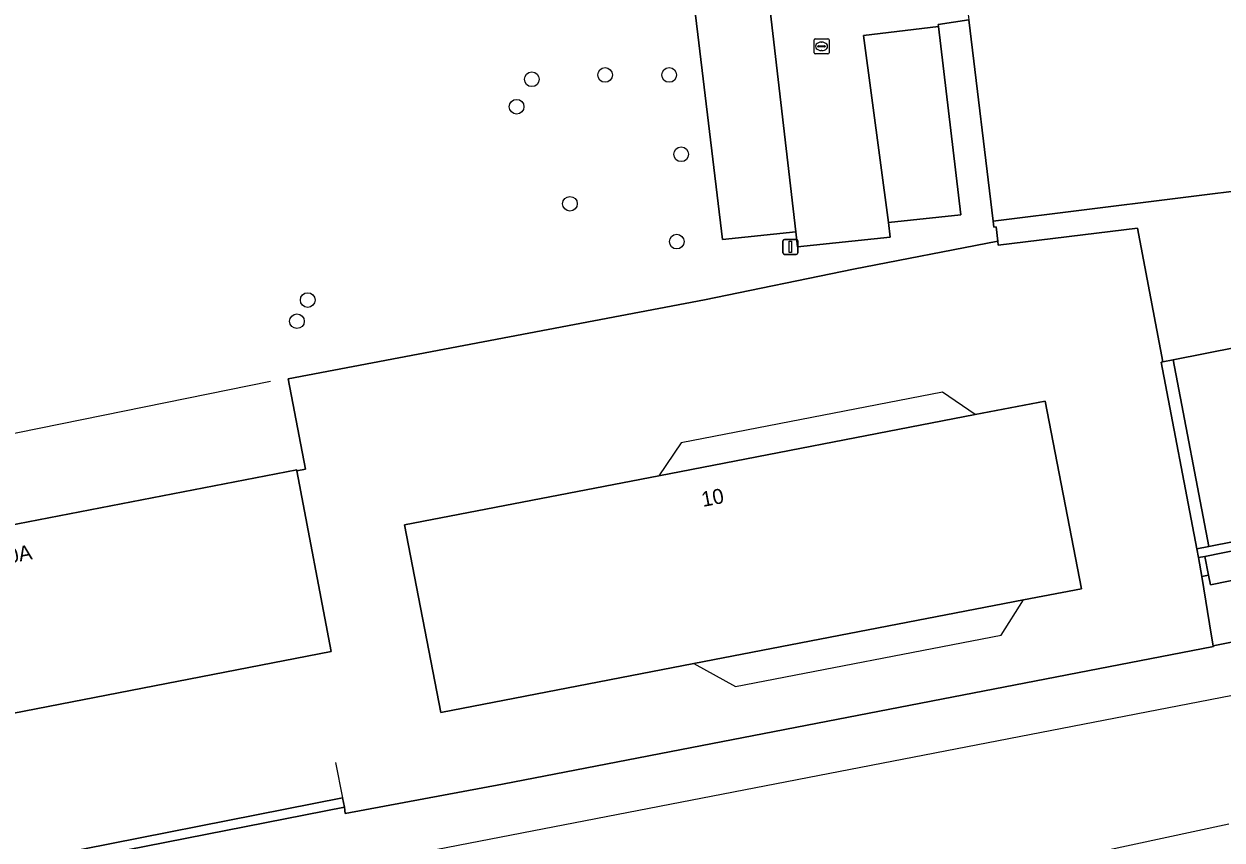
# Model space of a CAD drawing. Extents: x 161477 to 163040, y 383680 to 384871.
# Drawn here: x 161860.2 to 161940, y 383906.2 to 383960.6 of the extents above; entities that cross this region are included whole.
import ezdxf

# ---------------------------------------------------------------- set-up
doc = ezdxf.new("R2010")
doc.units = 0
for name, color, linetype in [('IMGEO_Boom', 7, 'Continuous'), ('IMGEO_Erf', 7, 'Continuous'), ('IMGEO_Groenvoorziening', 7, 'Continuous'), ('IMGEO_Hek', 7, 'Continuous'), ('IMGEO_Kolk', 7, 'Continuous'), ('IMGEO_Lichtmast', 7, 'Continuous'), ('IMGEO_Muur', 7, 'Continuous'), ('IMGEO_Pand', 7, 'Continuous'), ('IMGEO_Pand_nummerreeks', 7, 'Continuous'), ('IMGEO_Pand_overbouw', 7, 'Continuous'), ('IMGEO_Parkeervlak_halfverhard', 7, 'Continuous'), ('IMGEO_Parkeervlak_open', 7, 'Continuous'), ('IMGEO_Rijbaan_lokaal_open', 7, 'Continuous'), ('IMGEO_Spoor', 7, 'Continuous'), ('IMGEO_Spoorbaan_halfverhard', 7, 'Continuous'), ('IMGEO_Terreindeel_onvherhard', 7, 'Continuous'), ('IMGEO_Terreindeel_open', 7, 'Continuous')]:
    doc.layers.add(name, color=color, linetype=linetype)

msp = doc.modelspace()

# ---------------------------------------------------------------- linework, layer by layer
at = {"layer": 'IMGEO_Boom'}
for centre in [(161894.02, 383956.922), (161898.906, 383957.215), (161903.179, 383957.215), (161893.006, 383955.098), (161903.979, 383951.925), (161896.564, 383948.624), (161903.687, 383946.106), (161879.074, 383942.207), (161878.356, 383940.799)]:
    msp.add_circle(centre, 0.489, dxfattribs=at)
at = {"layer": 'IMGEO_Erf'}
for points in [[(161955.133, 383951.147), (161955.119, 383951.24), (161924.788, 383947.478), (161924.838, 383947.067), (161924.975, 383947.096), (161925.091, 383946.137), (161925.124, 383945.867), (161934.398, 383946.998), (161936.102, 383938.095), (161936.789, 383938.231), (161958.017, 383942.414), (161958.264, 383942.462), (161961.138, 383943.029), (161961.384, 383943.077), (161998.351, 383950.362), (161997.814, 383954.725), (161991.65, 383953.96), (161991.526, 383954.596)], [(161860.263, 383904.855), (161881.395, 383909.016), (161881.519, 383908.403), (161881.581, 383907.973), (161892.059, 383909.935), (161939.472, 383919.11), (161939.462, 383919.163), (161939.344, 383919.814), (161938.691, 383923.782), (161938.484, 383925.041), (161938.368, 383925.629), (161935.986, 383938.072), (161936.102, 383938.095), (161934.398, 383946.998), (161925.124, 383945.867), (161925.091, 383946.137), (161915.472, 383944.275), (161905.531, 383942.227), (161877.767, 383936.948), (161878.927, 383930.932), (161878.358, 383930.822), (161880.65, 383918.771), (161847.558, 383912.364)]]:
    msp.add_lwpolyline(points, dxfattribs=at)
msp.add_lwpolyline([(161885.532, 383927.22), (161902.479, 383930.5), (161923.583, 383934.576), (161928.25, 383935.475), (161930.667, 383922.963), (161926.814, 383922.219), (161904.821, 383917.977), (161887.951, 383914.722)], close=True, dxfattribs=at)
at = {"layer": 'IMGEO_Groenvoorziening'}
msp.add_lwpolyline([(161845.252, 383924.49), (161878.344, 383930.897), (161878.358, 383930.822), (161878.927, 383930.932), (161877.767, 383936.948), (161905.531, 383942.227), (161915.472, 383944.275), (161925.091, 383946.137), (161924.975, 383947.096), (161924.838, 383947.067), (161924.788, 383947.478), (161923.153, 383960.88), (161921.117, 383960.583), (161921.135, 383960.434), (161922.628, 383947.889), (161917.803, 383947.382), (161917.906, 383946.402), (161911.729, 383945.753), (161911.624, 383946.759), (161906.742, 383946.246), (161904.284, 383966.57)], dxfattribs=at)
at = {"layer": 'IMGEO_Hek'}
for points in [[(161856.984, 383932.82), (161876.595, 383936.812)], [(161877.767, 383936.948), (161878.662, 383932.306)], [(161878.662, 383932.306), (161878.927, 383930.932)], [(161878.927, 383930.932), (161878.306, 383930.812)], [(161880.918, 383911.379), (161881.395, 383909.016), (161881.519, 383908.403), (161881.581, 383907.973), (161892.059, 383909.935), (161939.472, 383919.11), (161939.462, 383919.163), (161939.344, 383919.814), (161938.691, 383923.782), (161938.484, 383925.041), (161938.368, 383925.629)], [(161824.037, 383897.352), (161831.558, 383898.701), (161834.037, 383899.213), (161860.382, 383904.241), (161881.519, 383908.403)]]:
    msp.add_lwpolyline(points, dxfattribs=at)
at = {"layer": 'IMGEO_Kolk'}
for p, q in [((161912.838, 383958.694), (161912.838, 383959.546)), ((161912.913, 383959.62), (161913.765, 383959.62)), ((161913.097, 383959.114), (161913.097, 383959.126)), ((161913.535, 383959.077), (161913.137, 383959.077)), ((161913.14, 383959.163), (161913.538, 383959.163)), ((161913.326, 383959.4), (161913.351, 383959.4)), ((161913.581, 383959.126), (161913.581, 383959.114)), ((161913.839, 383959.546), (161913.839, 383958.694)), ((161913.765, 383958.62), (161912.913, 383958.62)), ((161913.349, 383958.84), (161913.324, 383958.84))]:
    msp.add_line(p, q, dxfattribs=at)
for points in [[(161912.838, 383958.694), (161912.838, 383959.546)], [(161912.913, 383959.62), (161913.765, 383959.62)], [(161913.839, 383959.546), (161913.839, 383958.694)], [(161913.765, 383958.62), (161912.913, 383958.62)]]:
    msp.add_lwpolyline(points, dxfattribs=at)
for centre, radius, start, end in [((161912.915, 383959.544), 0.0765, 91.55205, 178.44795), ((161912.915, 383959.544), 0.0765, 91.55205, 178.44795), ((161913.137, 383959.123), 0.0403, 85.87752, 175.75265), ((161913.134, 383959.113), 0.0366, 178.93798, 274.71019), ((161913.538, 383959.12), 0.043, 264.86636, 352.45326), ((161913.542, 383959.125), 0.0386, 1.73085, 96.63898), ((161913.763, 383959.544), 0.0765, 1.55205, 88.44795), ((161913.763, 383959.544), 0.0765, 1.55205, 88.44795), ((161912.915, 383958.696), 0.0765, 181.55205, 268.44795), ((161912.915, 383958.696), 0.0765, 181.55205, 268.44795), ((161913.763, 383958.696), 0.0765, 271.55205, 358.44795), ((161913.763, 383958.696), 0.0765, 271.55205, 358.44795)]:
    msp.add_arc(centre, radius, start, end, dxfattribs=at)
for centre, major_axis, ratio, start_param, end_param in [((161913.325, 383959.12), (-0.387, 0.002), 0.722429, 4.712389, 7.853982), ((161913.35, 383959.12), (-0.39, 0.002), 0.717154, 1.570796, 4.712389)]:
    msp.add_ellipse(centre, major_axis=major_axis, ratio=ratio, start_param=start_param, end_param=end_param, dxfattribs=at)
at = {"layer": 'IMGEO_Lichtmast'}
for p, q in [((161910.768, 383945.351), (161910.768, 383946.151)), ((161910.768, 383946.151), (161910.768, 383945.351)), ((161910.868, 383946.251), (161911.658, 383946.251)), ((161911.658, 383946.251), (161910.868, 383946.251)), ((161911.758, 383946.151), (161911.758, 383945.351)), ((161911.758, 383945.351), (161911.758, 383946.151)), ((161911.658, 383945.251), (161910.868, 383945.251)), ((161910.868, 383945.251), (161911.658, 383945.251))]:
    msp.add_line(p, q, dxfattribs=at)
msp.add_lwpolyline([(161911.188, 383946.126), (161911.338, 383946.126), (161911.338, 383945.376), (161911.188, 383945.376), (161911.188, 383946.126)], dxfattribs=at)
for centre, start, end in [((161910.868, 383946.151), 90, 180), ((161910.868, 383946.151), 90, 180), ((161911.658, 383946.151), 0, 90), ((161911.658, 383946.151), 360, 90), ((161910.868, 383945.351), 180, 270), ((161910.868, 383945.351), 180, 270), ((161911.658, 383945.351), 270, 0), ((161911.658, 383945.351), 270, 0)]:
    msp.add_arc(centre, 0.1, start, end, dxfattribs=at)
at = {"layer": 'IMGEO_Muur'}
for points in [[(161925.091, 383946.137), (161915.472, 383944.275)], [(161915.472, 383944.275), (161905.531, 383942.227)], [(161877.767, 383936.948), (161905.531, 383942.227)]]:
    msp.add_lwpolyline(points, dxfattribs=at)
for points in [[(161938.368, 383925.629), (161938.484, 383925.041), (161938.9, 383925.123), (161941.418, 383925.619), (161962.129, 383929.698), (162010.959, 383938.916), (162010.903, 383939.211), (162010.847, 383939.506), (162000.031, 383937.464), (161962.015, 383930.287), (161939.172, 383925.788)], [(161939.172, 383925.788), (161936.789, 383938.231), (161936.102, 383938.095), (161935.986, 383938.072), (161938.368, 383925.629)]]:
    msp.add_lwpolyline(points, close=True, dxfattribs=at)
at = {"layer": 'IMGEO_Pand'}
msp.add_lwpolyline([(161949.098, 384000.565), (161949.412, 383998.153), (161949.604, 383996.676), (161950.476, 383989.986), (161944.534, 383989.254), (161939.601, 383988.646), (161939.204, 383988.597), (161939.001, 383990.24), (161919.858, 383987.878), (161922.541, 383965.891), (161923.153, 383960.88), (161924.788, 383947.478), (161955.119, 383951.24), (161955.133, 383951.147), (161955.356, 383949.45), (161969.073, 383951.131), (161968.408, 383956.619), (161965.92, 383976.575), (161964.461, 383988.274)], dxfattribs=at)
for points in [[(161930.667, 383922.963), (161928.25, 383935.475), (161923.583, 383934.576), (161902.479, 383930.5), (161885.532, 383927.22), (161887.951, 383914.722), (161904.821, 383917.977), (161926.814, 383922.219)], [(161878.358, 383930.822), (161878.344, 383930.897), (161845.252, 383924.49), (161840.505, 383923.57), (161840.343, 383923.539), (161842.649, 383911.413), (161847.558, 383912.364), (161880.65, 383918.771)]]:
    msp.add_lwpolyline(points, close=True, dxfattribs=at)
at = {"layer": 'IMGEO_Pand_overbouw'}
msp.add_lwpolyline([(161966.543, 383987.797), (161967.919, 383976.828), (161965.92, 383976.575), (161968.408, 383956.619), (161969.073, 383951.131), (161955.356, 383949.45), (161955.133, 383951.147), (161955.119, 383951.24), (161924.788, 383947.478), (161924.838, 383947.067), (161924.975, 383947.096), (161925.091, 383946.137), (161925.124, 383945.867), (161934.398, 383946.998), (161936.102, 383938.095), (161936.789, 383938.231), (161958.017, 383942.414), (161958.264, 383942.462), (161961.138, 383943.029), (161961.384, 383943.077), (161998.351, 383950.362), (161997.814, 383954.725), (161991.65, 383953.96), (161991.526, 383954.596)], dxfattribs=at)
for points in [[(161923.583, 383934.576), (161921.395, 383936.072), (161903.972, 383932.7), (161902.479, 383930.5)], [(161925.319, 383919.875), (161926.814, 383922.219), (161904.821, 383917.977), (161907.593, 383916.442)]]:
    msp.add_lwpolyline(points, close=True, dxfattribs=at)
at = {"layer": 'IMGEO_Parkeervlak_halfverhard'}
msp.add_lwpolyline([(161962.015, 383930.287), (162000.031, 383937.464), (162000, 383942.855), (161998.351, 383950.362), (161961.384, 383943.077), (161962.856, 383937.888), (161963.467, 383937.995), (161965.452, 383938.407), (161966.837, 383931.517), (161957.328, 383929.739), (161955.986, 383936.551), (161958.009, 383936.945), (161958.577, 383937.055), (161958.017, 383942.414), (161936.789, 383938.231), (161939.172, 383925.788)], close=True, dxfattribs=at)
at = {"layer": 'IMGEO_Parkeervlak_open'}
for points in [[(161909.262, 383967.093), (161904.284, 383966.57), (161906.742, 383946.246), (161911.624, 383946.759)], [(161921.135, 383960.434), (161916.144, 383959.841), (161917.803, 383947.382), (161922.628, 383947.889)]]:
    msp.add_lwpolyline(points, close=True, dxfattribs=at)
at = {"layer": 'IMGEO_Rijbaan_lokaal_open'}
msp.add_lwpolyline([(161909.262, 383967.093), (161911.624, 383946.759), (161911.729, 383945.753), (161917.906, 383946.402), (161917.803, 383947.382), (161916.144, 383959.841), (161921.135, 383960.434), (161921.117, 383960.583), (161923.153, 383960.88)], dxfattribs=at)
at = {"layer": 'IMGEO_Spoor'}
for points in [[(162082.223, 383940.616), (162067.156, 383939.077), (162060.654, 383938.31), (162050.143, 383936.843), (162039.55, 383934.981), (161761.259, 383881.105), (161737.229, 383876.551), (161717.526, 383872.756)], [(161940.49, 383907.276), (161906.48, 383899.966), (161883.869, 383895.635), (161863.414, 383892.09), (161749.217, 383872.993)]]:
    msp.add_lwpolyline(points, dxfattribs=at)
at = {"layer": 'IMGEO_Spoorbaan_halfverhard'}
msp.add_lwpolyline([(161944.398, 383920.135), (161939.462, 383919.163), (161939.472, 383919.11), (161892.059, 383909.935), (161881.581, 383907.973), (161881.519, 383908.403), (161860.382, 383904.241)], dxfattribs=at)
at = {"layer": 'IMGEO_Terreindeel_onvherhard'}
msp.add_lwpolyline([(161938.9, 383925.123), (161938.484, 383925.041), (161938.691, 383923.782), (161939.146, 383923.871)], close=True, dxfattribs=at)
at = {"layer": 'IMGEO_Terreindeel_open'}
for points in [[(161939.146, 383923.871), (161939.272, 383923.232), (161941.79, 383923.728), (161941.716, 383924.103), (161941.418, 383925.619), (161938.9, 383925.123)], [(161943.493, 383924.728), (161942.423, 383924.517), (161942.475, 383924.252), (161941.716, 383924.103), (161941.79, 383923.728), (161939.272, 383923.232), (161939.146, 383923.871), (161938.691, 383923.782), (161939.344, 383919.814), (161939.462, 383919.163), (161944.398, 383920.135)]]:
    msp.add_lwpolyline(points, close=True, dxfattribs=at)
msp.add_lwpolyline([(161860.382, 383904.241), (161881.519, 383908.403), (161881.395, 383909.016), (161860.263, 383904.855)], dxfattribs=at)

# ---------------------------------------------------------------- texts
at = {"layer": 'IMGEO_Pand_nummerreeks'}
for s, rotation, p in [('10', 10.76588, (161905.432, 383928.416)), ('10A', 10.76015, (161858.42, 383924.498))]:
    msp.add_text(s, height=1, rotation=rotation, dxfattribs=at).set_placement(p)

doc.saveas('drawing.dxf')
